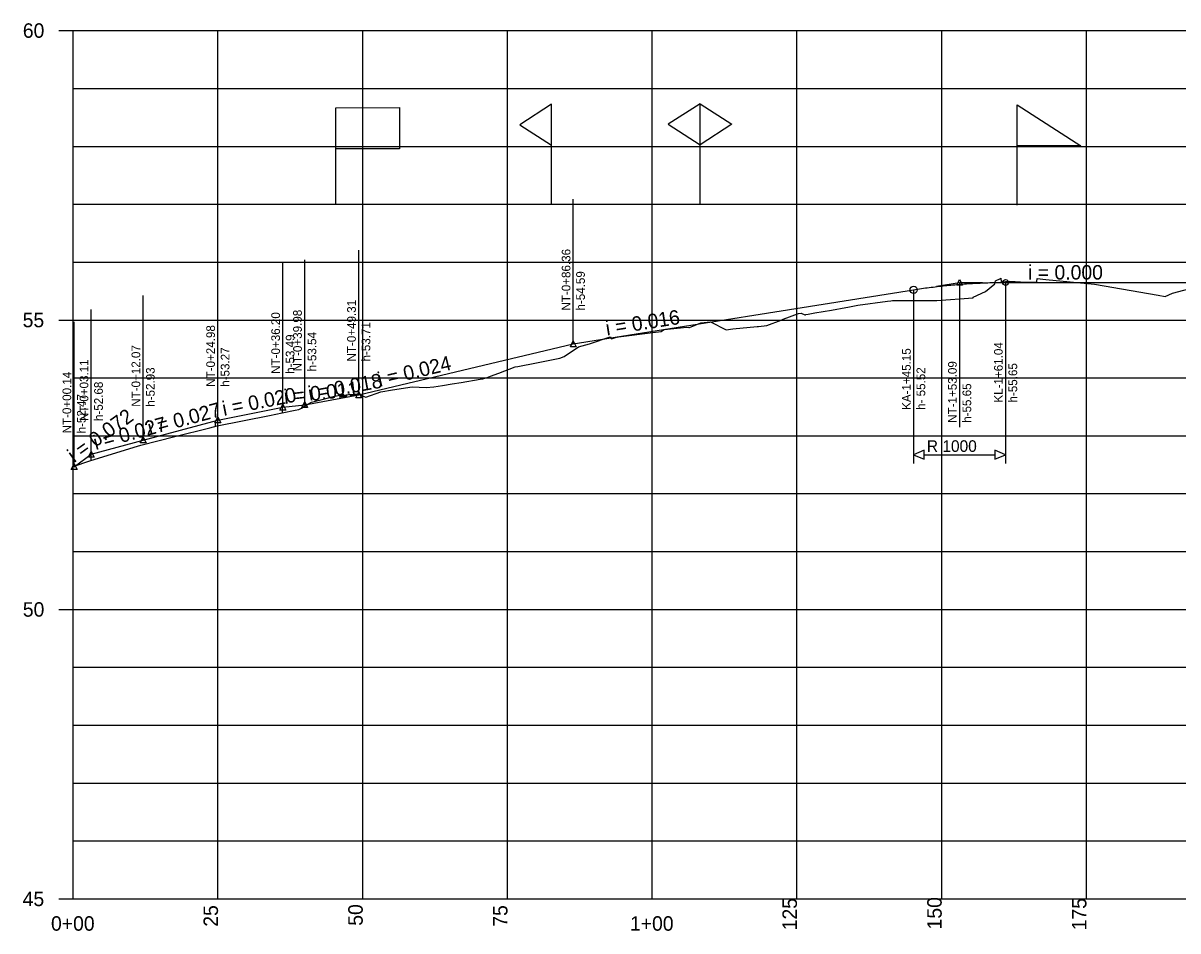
# Model space of a CAD drawing. Extents: x 655100 to 703495, y 6445581 to 6476602.
# Drawn here: x 669300.6 to 669500.1, y 6465864 to 6466020.9 of the extents above; entities that cross this region are included whole.
import ezdxf

# ---------------------------------------------------------------- set-up
doc = ezdxf.new("R2010")
doc.units = 0
for name, color, linetype in [('Level 25', 7, 'Continuous'), ('Level 6', 7, 'Continuous'), ('piirkitsendus', 7, 'Continuous'), ('Profile', 7, 'Continuous'), ('Prop Vertical Alignment', 7, 'Continuous')]:
    doc.layers.add(name, color=color, linetype=linetype)

msp = doc.modelspace()

# ---------------------------------------------------------------- linework, layer by layer
at = {"layer": 'Level 25'}
for points in [[(669354.67, 6465989.53), (669354.67, 6466006.24), (669365.66, 6466006.3), (669365.67, 6465999.16), (669354.66, 6465999.16)], [(669391.92, 6465989.48), (669391.92, 6466006.84), (669386.42, 6466003.3), (669391.93, 6465999.76)], [(669417.57, 6465989.57), (669417.57, 6466006.92), (669412.07, 6466003.39), (669417.58, 6465999.84)], [(669417.57, 6465989.57), (669417.57, 6466006.92), (669423.07, 6466003.39), (669417.56, 6465999.84)], [(669472.36, 6465989.4), (669472.36, 6466006.75), (669483.36, 6465999.68), (669472.35, 6465999.67)]]:
    msp.add_lwpolyline(points, dxfattribs=at)
at = {"layer": 'Level 6'}
msp.add_lwpolyline([(669309.3, 6465944.24), (669309.31, 6465944.24), (669312.18, 6465945.25), (669319.82, 6465947.59), (669320.95, 6465947.95), (669326.82, 6465949.44), (669332.92, 6465950.96), (669334.14, 6465951.28), (669343.19, 6465953.08), (669345.4, 6465953.52), (669347.61, 6465953.97), (669348.28, 6465954.1), (669348.71, 6465954.35), (669349.83, 6465955.01), (669350.46, 6465955.38), (669352.04, 6465955.79), (669354.25, 6465956.34), (669355.04, 6465956.54), (669356.46, 6465956.65), (669356.82, 6465956.68), (669358.49, 6465956.84), (669358.58, 6465956.85), (669359, 6465956.61), (669359.85, 6465956.25), (669362.44, 6465957.18), (669364.46, 6465957.5), (669367.84, 6465958), (669370.24, 6465957.9), (669371.57, 6465958.02), (669373.06, 6465958.25), (669374.76, 6465958.52), (669376.31, 6465958.78), (669379.57, 6465959.33), (669380.06, 6465959.42), (669380.77, 6465959.63), (669381.38, 6465959.85), (669382.82, 6465960.39), (669385.63, 6465961.46), (669386.07, 6465961.54), (669389.33, 6465962.19), (669393.35, 6465963), (669394.11, 6465963.26), (669396.57, 6465964.93), (669398.45, 6465965.48), (669402.05, 6465966.64), (669402.25, 6465966.3), (669403.32, 6465966.66), (669403.35, 6465966.62), (669403.45, 6465966.65), (669409.43, 6465967.41), (669410.85, 6465967.6), (669411.35, 6465967.91), (669415.29, 6465968.35), (669415.62, 6465968.27), (669415.74, 6465968.25), (669417.68, 6465969.06), (669419.37, 6465969.23), (669422.1, 6465967.85), (669423.25, 6465968.06), (669427.44, 6465968.45), (669427.68, 6465968.43), (669429.08, 6465968.63), (669431.6, 6465969.57), (669431.9, 6465969.71), (669434.55, 6465970.71), (669434.56, 6465970.71), (669435.03, 6465970.76), (669435.68, 6465970.49), (669435.75, 6465970.49), (669435.83, 6465970.51), (669436.21, 6465970.58), (669437.4, 6465970.79), (669440.24, 6465971.29), (669442.73, 6465971.74), (669443.08, 6465971.8), (669444.84, 6465972.14), (669449.95, 6465972.81), (669450.51, 6465972.88), (669450.83, 6465972.95), (669457.54, 6465972.96), (669458.48, 6465972.95), (669464.73, 6465973.39), (669464.76, 6465973.49), (669466.87, 6465974.48), (669468.5, 6465975.79), (669468.59, 6465976.33), (669469.44, 6465976.76), (669469.52, 6465976.81), (669469.59, 6465976.15), (669471.08, 6465976.27), (669473.83, 6465976.12), (669475.7, 6465976.18), (669475.72, 6465976.2), (669475.8, 6465976.74), (669477.3, 6465976.58), (669485.7, 6465975.76), (669496.67, 6465973.88), (669497.9, 6465973.64), (669499.16, 6465974.21), (669506.12, 6465976.05)], dxfattribs=at)
at = {"layer": 'piirkitsendus'}
for p, q in [((669345.42, 6465953.58), (669345.42, 6465954.52)), ((669333.87, 6465951.23), (669333.87, 6465952.17)), ((669312.42, 6465945.32), (669312.42, 6465946.26))]:
    msp.add_line(p, q, dxfattribs=at)
at = {"layer": 'Profile'}
for p, q in [((669306.8, 6466019.57), (669311.8, 6466019.57)), ((669306.8, 6466019.57), (669311.8, 6466019.57)), ((669309.3, 6465869.57), (669309.3, 6466019.57)), ((669309.3, 6466019.57), (670209.3, 6466019.57)), ((669309.3, 6466019.57), (670209.3, 6466019.57)), ((669334.3, 6465869.57), (669334.3, 6466019.57)), ((669359.3, 6465869.57), (669359.3, 6466019.57)), ((669384.3, 6465869.57), (669384.3, 6466019.57)), ((669409.3, 6465869.57), (669409.3, 6466019.57)), ((669434.3, 6465869.57), (669434.3, 6466019.57)), ((669459.3, 6465869.57), (669459.3, 6466019.57)), ((669484.3, 6465869.57), (669484.3, 6466019.57)), ((669309.3, 6466009.57), (669310.55, 6466009.57)), ((669309.3, 6466009.57), (670209.3, 6466009.57)), ((669309.3, 6465999.57), (669310.55, 6465999.57)), ((669309.3, 6465999.57), (670209.3, 6465999.57)), ((669309.3, 6465989.57), (669310.55, 6465989.57)), ((669309.3, 6465989.57), (670209.3, 6465989.57)), ((669309.3, 6465979.57), (669310.55, 6465979.57)), ((669309.3, 6465979.57), (670209.3, 6465979.57)), ((669306.8, 6465969.57), (669311.8, 6465969.57)), ((669309.3, 6465969.57), (670209.3, 6465969.57)), ((669309.3, 6465959.57), (669310.55, 6465959.57)), ((669309.3, 6465959.57), (670209.3, 6465959.57)), ((669309.3, 6465949.57), (669310.55, 6465949.57)), ((669309.3, 6465949.57), (670209.3, 6465949.57)), ((669309.3, 6465939.57), (669310.55, 6465939.57)), ((669309.3, 6465939.57), (670209.3, 6465939.57)), ((669309.3, 6465929.57), (669310.55, 6465929.57)), ((669309.3, 6465929.57), (670209.3, 6465929.57)), ((669306.8, 6465919.57), (669311.8, 6465919.57)), ((669309.3, 6465919.57), (670209.3, 6465919.57)), ((669309.3, 6465909.57), (669310.55, 6465909.57)), ((669309.3, 6465909.57), (670209.3, 6465909.57)), ((669309.3, 6465899.57), (669310.55, 6465899.57)), ((669309.3, 6465899.57), (670209.3, 6465899.57)), ((669309.3, 6465889.57), (669310.55, 6465889.57)), ((669309.3, 6465889.57), (670209.3, 6465889.57)), ((669309.3, 6465879.57), (669310.55, 6465879.57)), ((669309.3, 6465879.57), (670209.3, 6465879.57)), ((669306.8, 6465869.57), (669311.8, 6465869.57)), ((669309.3, 6465869.57), (670209.3, 6465869.57))]:
    msp.add_line(p, q, dxfattribs=at)
at = {"layer": 'Prop Vertical Alignment'}
for p, q in [((669395.67, 6465970.45), (669395.67, 6465990.45)), ((669358.61, 6465961.65), (669358.61, 6465981.65)), ((669345.51, 6465959.52), (669345.51, 6465979.52)), ((669349.28, 6465959.94), (669349.28, 6465979.94)), ((669334.28, 6465957.28), (669334.28, 6465977.28)), ((669395.67, 6465965.45), (669454.46, 6465974.79)), ((669454.46, 6465974.79), (669454.46, 6465969.79)), ((669454.46, 6465974.79), (669454.46, 6465944.79)), ((669458.43, 6465975.42), (669462.4, 6465976.06)), ((669462.4, 6465976.06), (669466.37, 6465976.06)), ((669462.4, 6465976.06), (669462.4, 6465971.06)), ((669470.34, 6465976.06), (669470.34, 6465971.06)), ((669470.34, 6465976.06), (669509.25, 6465976.06)), ((669470.34, 6465976.06), (669470.34, 6465944.79)), ((669321.37, 6465953.83), (669321.37, 6465973.83)), ((669312.41, 6465951.37), (669312.41, 6465971.37)), ((669395.67, 6465965.45), (669395.67, 6465970.45)), ((669462.4, 6465971.06), (669462.4, 6465951.06)), ((669470.34, 6465971.06), (669470.34, 6465954.56)), ((669309.45, 6465949.23), (669309.45, 6465969.23)), ((669454.46, 6465969.79), (669454.46, 6465953.29)), ((669358.61, 6465956.65), (669395.67, 6465965.45)), ((669358.61, 6465956.65), (669358.61, 6465961.65)), ((669345.51, 6465954.52), (669345.51, 6465959.52)), ((669349.28, 6465954.94), (669349.28, 6465959.94)), ((669334.28, 6465952.28), (669334.28, 6465957.28)), ((669349.28, 6465954.94), (669358.61, 6465956.65)), ((669334.28, 6465952.28), (669345.51, 6465954.52)), ((669345.51, 6465954.52), (669349.28, 6465954.94)), ((669321.37, 6465948.83), (669321.37, 6465953.83)), ((669321.37, 6465948.83), (669334.28, 6465952.28)), ((669312.41, 6465946.37), (669312.41, 6465951.37)), ((669309.45, 6465944.23), (669309.45, 6465949.23)), ((669312.41, 6465946.37), (669321.37, 6465948.83)), ((669309.45, 6465944.23), (669312.41, 6465946.37))]:
    msp.add_line(p, q, dxfattribs=at)
for points in [[(669462.4, 6465976.56), (669462.9, 6465975.56), (669461.9, 6465975.56)], [(669395.67, 6465965.95), (669396.17, 6465964.95), (669395.17, 6465964.95)], [(669358.61, 6465957.15), (669359.11, 6465956.15), (669358.11, 6465956.15)], [(669345.51, 6465955.02), (669346.01, 6465954.02), (669345.01, 6465954.02)], [(669349.28, 6465955.44), (669349.78, 6465954.44), (669348.78, 6465954.44)], [(669334.28, 6465952.78), (669334.78, 6465951.78), (669333.78, 6465951.78)], [(669321.37, 6465949.33), (669321.87, 6465948.33), (669320.87, 6465948.33)], [(669312.41, 6465946.87), (669312.91, 6465945.87), (669311.91, 6465945.87)], [(669454.46, 6465946.29), (669456.3, 6465945.53), (669456.3, 6465947.06)], [(669470.34, 6465946.29), (669468.5, 6465947.06), (669468.5, 6465945.53)], [(669309.45, 6465944.73), (669309.95, 6465943.73), (669308.95, 6465943.73)]]:
    msp.add_lwpolyline(points, close=True, dxfattribs=at)
for points in [[(669454.46, 6465974.79), (669454.79, 6465974.85), (669455.13, 6465974.9), (669455.47, 6465974.95), (669455.81, 6465975), (669456.15, 6465975.05), (669456.48, 6465975.1), (669456.82, 6465975.14), (669457.16, 6465975.19), (669457.5, 6465975.23), (669457.84, 6465975.27), (669458.17, 6465975.32), (669458.51, 6465975.36), (669458.85, 6465975.4), (669459.19, 6465975.43), (669459.53, 6465975.47), (669459.86, 6465975.51), (669460.2, 6465975.54), (669460.54, 6465975.58), (669460.88, 6465975.61), (669461.22, 6465975.64), (669461.55, 6465975.67), (669461.89, 6465975.7), (669462.23, 6465975.73), (669462.57, 6465975.75), (669462.91, 6465975.78), (669463.24, 6465975.8), (669463.58, 6465975.83), (669463.92, 6465975.85), (669464.26, 6465975.87), (669464.6, 6465975.89), (669464.93, 6465975.91), (669465.27, 6465975.93), (669465.61, 6465975.94), (669465.95, 6465975.96), (669466.29, 6465975.97), (669466.63, 6465975.99), (669466.96, 6465976), (669467.3, 6465976.01), (669467.64, 6465976.02), (669467.98, 6465976.03), (669468.32, 6465976.04), (669468.65, 6465976.04), (669468.99, 6465976.05), (669469.33, 6465976.05), (669469.67, 6465976.05), (669470.01, 6465976.06), (669470.34, 6465976.06)], [(669456.3, 6465946.29), (669468.5, 6465946.29)]]:
    msp.add_lwpolyline(points, dxfattribs=at)
for centre, radius in [((669470.34, 6465976.06), 0.5), ((669454.46, 6465974.79), 0.625)]:
    msp.add_circle(centre, radius, dxfattribs=at)

# ---------------------------------------------------------------- texts
at = {"layer": 'Profile'}
for s, p in [('60', (669300.59, 6466018.32)), ('60', (669300.59, 6466018.32)), ('55', (669300.56, 6465968.32)), ('50', (669300.59, 6465918.32)), ('45', (669300.56, 6465868.32)), ('0+00', (669305.46, 6465864.07)), ('1+00', (669405.46, 6465864.07))]:
    msp.add_text(s, height=2.5, dxfattribs=at).set_placement(p)
for s, p in [('50', (669359.3, 6465864.93)), ('125', (669434.3, 6465864.14)), ('150', (669459.3, 6465864.3)), ('175', (669484.3, 6465864.14)), ('25', (669334.3, 6465864.76)), ('75', (669384.3, 6465864.76))]:
    msp.add_text(s, height=2.5, rotation=90, dxfattribs=at).set_placement(p)
at = {"layer": 'Prop Vertical Alignment'}
for s, height, rotation, p in [('NT-0+86.36', 1.5, 90, (669395.17, 6465971.2)), ('i = 0.000', 2.5, 360, (669474.23, 6465976.56)), ('h-54.59', 1.5, 90, (669397.67, 6465971.2)), ('NT-0+49.31', 1.5, 90, (669358.11, 6465962.4)), ('NT-0+36.20', 1.5, 90, (669345.01, 6465960.27)), ('NT-0+39.98', 1.5, 90, (669348.78, 6465960.69)), ('i = 0.016', 2.5, 9.0293, (669401.47, 6465966.88)), ('NT-0+24.98', 1.5, 90, (669333.78, 6465958.03)), ('h-53.71', 1.5, 90, (669360.61, 6465962.4)), ('h-53.49', 1.5, 90, (669347.51, 6465960.27)), ('h-53.54', 1.5, 90, (669351.28, 6465960.69)), ('NT-0+12.07', 1.5, 90, (669320.87, 6465954.58)), ('h-53.27', 1.5, 90, (669336.28, 6465958.03)), ('KA-1+45.15', 1.5, 90, (669453.96, 6465954.04)), ('KL-1+61.04', 1.5, 90, (669469.84, 6465955.31)), ('NT-0+03.11', 1.5, 90, (669311.91, 6465952.12)), ('i = 0.024', 2.5, 13.3619, (669362.2, 6465958.02)), ('NT-1+53.09', 1.5, 90, (669461.9, 6465951.81)), ('NT-0+00.14', 1.5, 90, (669308.95, 6465949.98)), ('h-52.93', 1.5, 90, (669323.37, 6465954.58)), ('i = 0.018', 2.5, 10.356, (669350.12, 6465955.61)), ('h- 55.52', 1.5, 90, (669456.46, 6465954.04)), ('h-55.65', 1.5, 90, (669472.34, 6465955.31)), ('h-52.68', 1.5, 90, (669314.41, 6465952.12)), ('i = 0.011', 2.5, 6.4933, (669345.83, 6465955.06)), ('h-55.65', 1.5, 90, (669464.4, 6465951.81)), ('h-52.47', 1.5, 90, (669311.45, 6465949.98)), ('i = 0.020', 2.5, 11.2466, (669335.31, 6465953)), ('i = 0.027', 2.5, 14.9756, (669322.53, 6465949.66)), ('i = 0.072', 2.5, 35.7645, (669309.45, 6465944.85)), ('i = 0.027', 2.5, 15.3471, (669313.17, 6465947.1))]:
    msp.add_text(s, height=height, rotation=rotation, dxfattribs=at).set_placement(p)
msp.add_text('R 1000', height=2, dxfattribs=at).set_placement((669456.74, 6465946.79))

doc.saveas('drawing.dxf')
